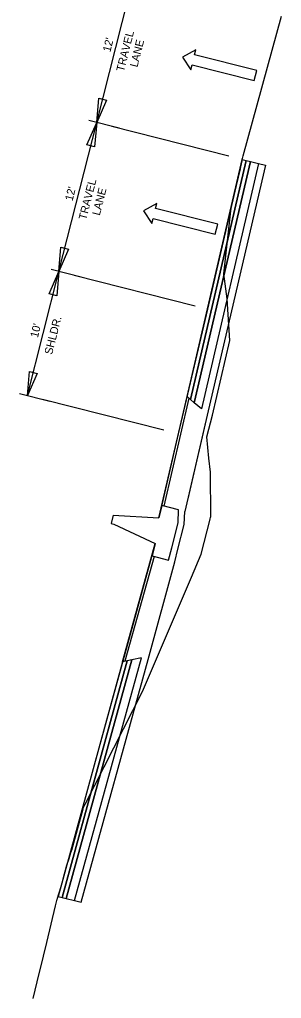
# Model space of a CAD drawing. Extents: x 670006 to 670131, y 737833 to 738003.
# Drawn here: x 670083.4 to 670103.8, y 737833.2 to 737909.7 of the extents above; entities that cross this region are included whole.
import ezdxf

# ---------------------------------------------------------------- set-up
doc = ezdxf.new("R2010")
doc.units = 0
for name, color, linetype in [('R_Alt Surface', 7, 'Continuous'), ('R_Exist Surface', 7, 'Continuous'), ('R_Fin Surface', 7, 'Continuous'), ('R_MOT', 7, 'Continuous'), ('R_SIGN_ANNOT', 7, 'Continuous')]:
    doc.layers.add(name, color=color, linetype=linetype)

msp = doc.modelspace()

# ---------------------------------------------------------------- linework, layer by layer
for points in [[(670093.961, 737868.739), (670093.715, 737867.77), (670095.008, 737867.442), (670095.254, 737868.411), (670095.745, 737870.35), (670095.777, 737871.373), (670094.484, 737871.701), (670094.238, 737870.732)], [(670090.681, 737870.943), (670090.681, 737870.943), (670090.519, 737870.303), (670090.733, 737870.249)], [(670090.681, 737870.943), (670094.238, 737870.732)], [(670090.733, 737870.249), (670093.961, 737868.739)]]:
    msp.add_lwpolyline(points)
at = {"layer": 'R_Alt Surface'}
for points in [[(670102.033, 737898.406), (670102.558, 737898.273), (670098.099, 737879.113), (670096.269, 737871.249)], [(670102.033, 737898.406), (670102.558, 737898.273), (670098.099, 737879.113), (670096.496, 737872.223)], [(670095.5, 737867.317), (670095.738, 737868.288), (670096.23, 737870.227), (670096.269, 737871.249)], [(670087.667, 737840.85), (670088.192, 737840.717), (670093.404, 737859.686), (670095.5, 737867.317)]]:
    msp.add_lwpolyline(points, dxfattribs=at)
for points in [[(670101.067, 737898.651), (670101.387, 737898.57), (670097.009, 737879.735), (670096.726, 737879.979)], [(670101.387, 737898.57), (670102.033, 737898.406), (670097.576, 737879.246), (670097.009, 737879.735)], [(670087.021, 737841.014), (670087.667, 737840.85), (670092.88, 737859.819), (670092.148, 737859.659)], [(670086.701, 737841.095), (670087.021, 737841.014), (670092.148, 737859.659), (670091.784, 737859.579)]]:
    msp.add_lwpolyline(points, close=True, dxfattribs=at)
at = {"layer": 'R_Exist Surface'}
msp.add_lwpolyline([(670084.448, 737833.213), (670084.758, 737834.497), (670085.243, 737836.522), (670085.503, 737837.576), (670086.191, 737840.434), (670086.321, 737840.96), (670086.331, 737840.993), (670086.35, 737841.051), (670086.453, 737841.389), (670086.656, 737842.033), (670086.792, 737842.559), (670087.08, 737843.623), (670087.242, 737844.142), (670087.382, 737844.612), (670087.427, 737844.727), (670087.461, 737844.798), (670088.34, 737848.023), (670088.367, 737848.124), (670088.494, 737848.388), (670092.96, 737857.187), (670096.784, 737866.12), (670097.557, 737867.896), (670098.248, 737870.648), (670098.282, 737870.787), (670098.29, 737870.834), (670098.276, 737874.308), (670098.153, 737875.393), (670097.992, 737877.08), (670098.437, 737878.775), (670099.774, 737884.585), (670099.569, 737887.849), (670099.32, 737889.801), (670099.846, 737894.48), (670099.892, 737894.893), (670099.892, 737894.903), (670099.9, 737894.935), (670100.271, 737896.608), (670100.292, 737896.698), (670100.613, 737898), (670100.618, 737898.028), (670100.736, 737898.676), (670100.757, 737898.784), (670100.759, 737898.798), (670100.817, 737899.009), (670103.807, 737909.911)], dxfattribs=at)
at = {"layer": 'R_Fin Surface'}
for points in [[(670100.747, 737898.732), (670098.029, 737887.042), (670095.765, 737877.299), (670094.238, 737870.732)], [(670096.585, 737880.1), (670094.646, 737871.66), (670094.484, 737871.701), (670094.238, 737870.732), (670096.444, 737880.222), (670096.585, 737880.1)], [(670093.961, 737868.739), (670092.216, 737862.393), (670089.564, 737852.749), (670086.381, 737841.176)], [(670091.42, 737859.5), (670093.961, 737868.739), (670093.715, 737867.77), (670093.877, 737867.729), (670091.602, 737859.539), (670091.42, 737859.5)]]:
    msp.add_lwpolyline(points, dxfattribs=at)
for points in [[(670100.747, 737898.732), (670101.067, 737898.651), (670096.726, 737879.979), (670096.444, 737880.222)], [(670086.381, 737841.176), (670086.701, 737841.095), (670091.784, 737859.579), (670091.42, 737859.5)]]:
    msp.add_lwpolyline(points, close=True, dxfattribs=at)
at = {"layer": 'R_MOT'}
for p, q in [((670097.137, 737907.292), (670096.09, 737906.732)), ((670097.039, 737906.904), (670097.137, 737907.292)), ((670096.09, 737906.732), (670096.744, 737905.741)), ((670101.882, 737905.676), (670097.039, 737906.904)), ((670096.744, 737905.741), (670096.842, 737906.129)), ((670096.842, 737906.129), (670101.685, 737904.9)), ((670101.685, 737904.9), (670101.882, 737905.676)), ((670094.092, 737895.284), (670093.045, 737894.724)), ((670093.994, 737894.896), (670094.092, 737895.284)), ((670098.836, 737893.668), (670093.994, 737894.896)), ((670093.045, 737894.724), (670093.699, 737893.733)), ((670093.699, 737893.733), (670093.797, 737894.121)), ((670093.797, 737894.121), (670098.639, 737892.892)), ((670098.639, 737892.892), (670098.836, 737893.668))]:
    msp.add_line(p, q, dxfattribs=at)
at = {"layer": 'R_SIGN_ANNOT'}
for p, q in [((670089.396, 737901.611), (670092.346, 737913.243)), ((670091.147, 737901.167), (670088.79, 737901.765)), ((670086.446, 737889.98), (670089.396, 737901.611)), ((670099.714, 737898.994), (670090.578, 737901.312)), ((670083.988, 737880.286), (670086.446, 737889.98)), ((670088.197, 737889.535), (670085.84, 737890.133)), ((670097.092, 737887.279), (670087.628, 737889.68)), ((670085.739, 737879.842), (670083.382, 737880.44)), ((670094.634, 737877.586), (670085.169, 737879.987))]:
    msp.add_line(p, q, dxfattribs=at)
for points in [[(670090.16, 737903.352), (670089.396, 737901.611), (670089.554, 737903.506)], [(670088.632, 737899.871), (670089.396, 737901.611), (670089.238, 737899.717)], [(670087.21, 737891.72), (670086.446, 737889.98), (670086.604, 737891.874)], [(670085.682, 737888.239), (670086.446, 737889.98), (670086.288, 737888.085)], [(670084.752, 737882.027), (670083.988, 737880.286), (670084.146, 737882.181)]]:
    msp.add_lwpolyline(points, close=True, dxfattribs=at)

# ---------------------------------------------------------------- texts
for s, p in [('TRAVEL', (670091.516, 737905.543)), ("12'", (670090.462, 737907.084)), ('LANE', (670092.571, 737905.89)), ("12'", (670087.512, 737895.452)), ('TRAVEL', (670088.579, 737893.965)), ('LANE', (670089.634, 737894.312)), ("10'", (670084.802, 737884.766)), ('SHLDR.', (670085.912, 737883.447))]:
    msp.add_text(s, height=0.625, rotation=75.76855, dxfattribs=at).set_placement(p)

doc.saveas('drawing.dxf')
